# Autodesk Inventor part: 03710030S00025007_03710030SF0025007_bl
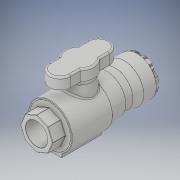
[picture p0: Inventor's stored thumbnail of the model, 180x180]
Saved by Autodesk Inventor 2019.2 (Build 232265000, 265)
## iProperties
Created: 2022-04
Part Number: 03710030S00025007_03710030SF0025007_bl
Material: Generic
Description: PA Ball Valve Series 1 25mm x Female 3/4''
Document SubType Name: Modeling
Designer: Lenora
Density: 1 g/cm^3
Appearance: Default
Author: Lenora
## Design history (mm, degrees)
derived "0371003.ipt"
feature "Solid1::0371003.ipt" dims "ScaleForDerivedMember" = 10
tag "TaggingFeature1"
body "Solid1"
other parameters: "d" = 25 [user parameter], "A1" = 27 [user parameter], "A2" = 54 [user parameter], "H_" = 129 [user parameter], "E_" = 53 [user parameter], "E1" = 47 [user parameter], "B" = 36 [user parameter], "l2" = 19 [user parameter], "Rc" = 26.441 [user parameter], "d0" = 129 [user parameter], "d16" = 77.4 [user parameter], "d19" = 1 [user parameter], "d20" = 32.25 [user parameter], "d22" = 85 deg [user parameter], "d25" = 1 [user parameter], "d34" = 23.22 [user parameter], "d35" = 12.9 [user parameter], "d37" = 0 [user parameter], "d39" = 360 deg [user parameter], "d43" = 27 [user parameter], "d45" = 70 deg [user parameter], "d46" = 70 deg [user parameter], "d48" = 0 [user parameter], "d57" = 2 [user parameter], "d63" = 53 [user parameter], "d71" = 6.45 [user parameter], "d72" = 9.675 [user parameter], "d73" = 23.22 [user parameter], "d76" = 54 [user parameter], "d77" = 16.2 [user parameter], "d78" = 34.83 [user parameter], "d79" = 16.125 [user parameter], "d80" = 100 deg [user parameter], "d81" = 10.965 [user parameter], "d83" = 22.95 [user parameter], "d84" = 9.675 [user parameter], "d85" = 26.5 [user parameter], "d90" = 0 [user parameter], "d91" = 7.95 [user parameter], "d92" = 45 deg [user parameter], "d93" = 4.24 [user parameter], "d94" = 1.696 [user parameter], "d95" = 2.12 [user parameter], "d96" = 2.12 [user parameter], "d97" = 2.12 [user parameter], "d98" = 2.12 [user parameter], "d111" = 0.5 [user parameter], "d112" = 2 [user parameter], "d114" = 7.42 [user parameter], "d115" = 0 [user parameter], "d117" = 360 deg [user parameter], "d119" = 42.93 [user parameter], "d120" = 47 [user parameter], "d121" = 25 [user parameter], "d122" = 1 [user parameter], "d123" = 89 deg [user parameter], "d124" = 80 deg [user parameter], "d125" = 36 [user parameter], "d127" = 15.2 [user parameter], "d132" = 49.29 [user parameter], "d134" = 0 [user parameter], "d135" = 0.25 [user parameter], "d138" = 26.441 [user parameter], "d139" = 19 [user parameter]
